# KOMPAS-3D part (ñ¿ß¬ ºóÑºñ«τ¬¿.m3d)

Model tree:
1. Эскиз:1
2. Операция выдавливания:1
     Расстояние 1 = 2; Расстояние 2 = 11
3. Эскиз:2
4. Вырезать элемент выдавливания:1
     Расстояние 1 = 2
5. Эскиз:3
6. Вырезать элемент выдавливания:2
     Расстояние 1 = 2
7. Массив по концентрической сетке:1  (with: Вырезать элемент выдавливания:2)  (labels: Экземпляр ( 1, 1 ); Экземпляр ( 1, 2 ); Экземпляр ( 1, 3 ); Экземпляр ( 1, 4 ))
     N 2 = 12; Шаг 2 = 360; Номер 2 = 1
8. Скругление:1
     Радиус = 0.2
9. Скругление:2
     Радиус = 0.2
10. Скругление:3
     Радиус = 1

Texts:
  stalker61
  Сплав АЛ8  ГОСТ 1583-93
